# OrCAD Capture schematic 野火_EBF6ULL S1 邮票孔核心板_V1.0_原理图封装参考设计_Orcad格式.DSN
size B; title: 野火_EBF6ULL S1 邮票孔核心板; rev: V1.0; note: MCU_连接器
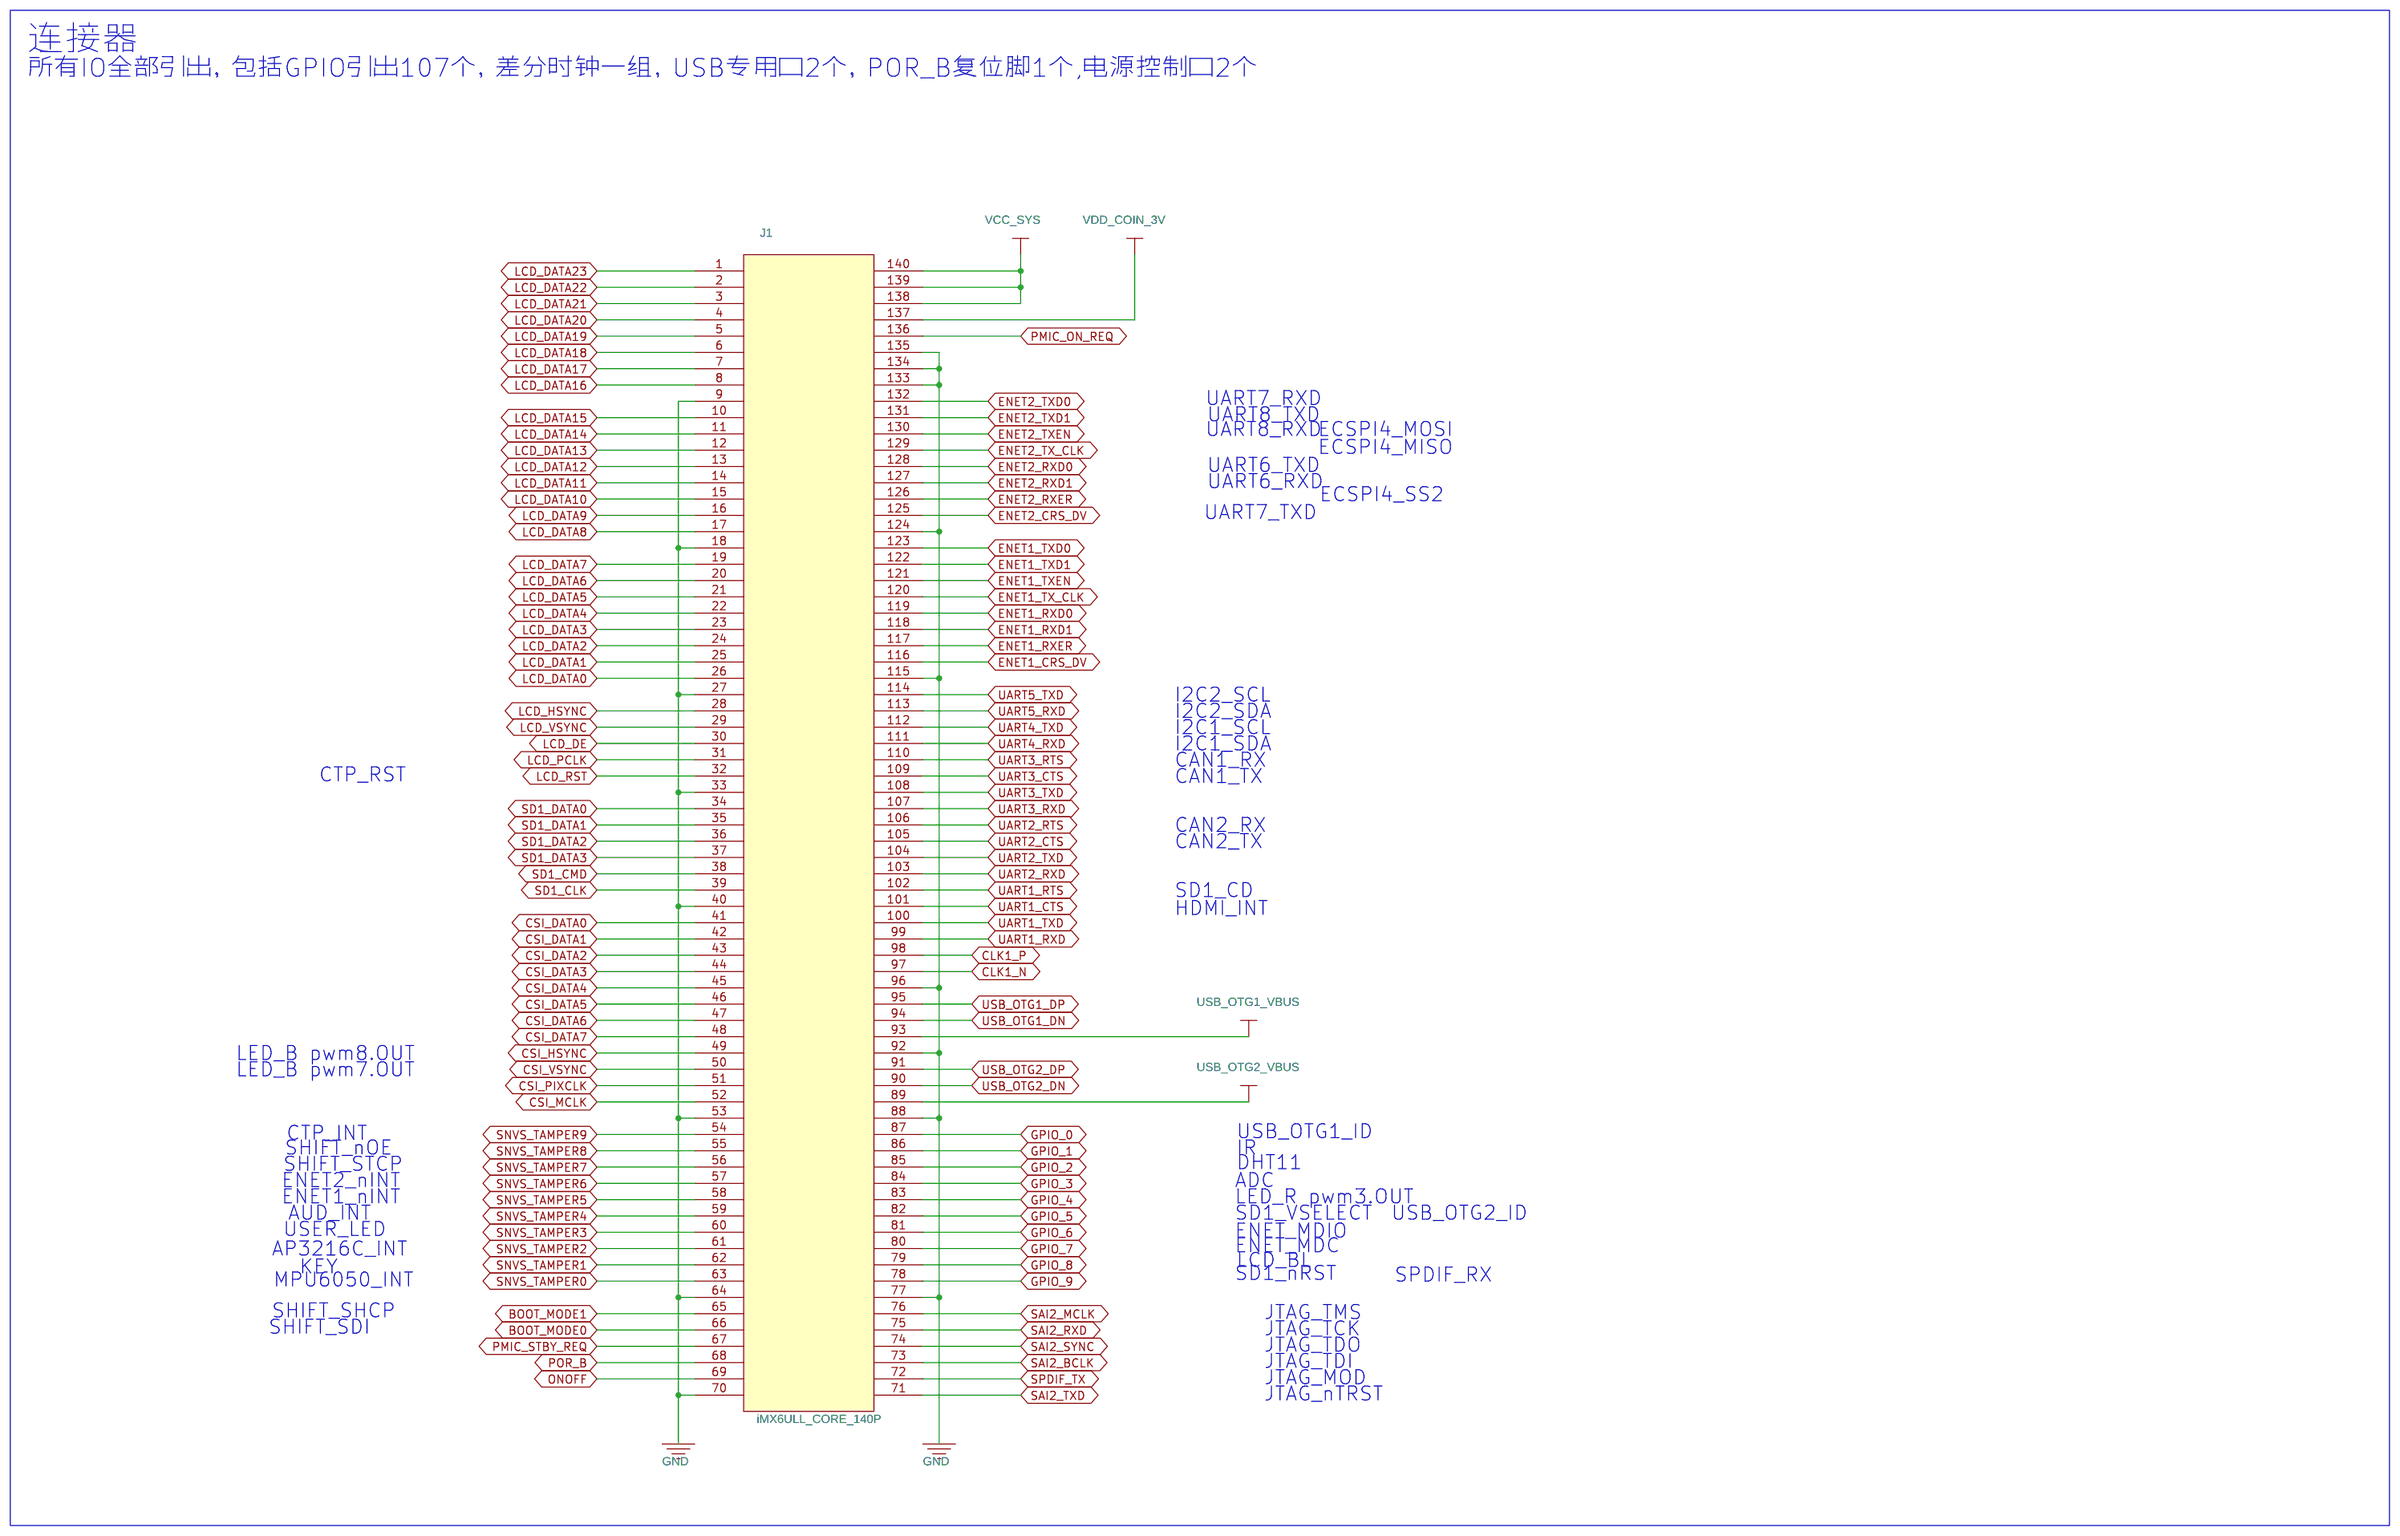
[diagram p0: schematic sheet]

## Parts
J1  iMX6ULL_CORE_140P  [6ULL_CORE_140P_39X39]

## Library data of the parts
J1 = iMX6ULL_CORE_140P

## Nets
GND: J1.9 J1.18 J1.27 J1.33 J1.40 J1.53 J1.64 J1.70 J1.77 J1.88 J1.92 J1.96 J1.115 J1.124 J1.133 J1.134 J1.135
VCC_SYS: J1.138 J1.139 J1.140
VDD_COIN_3V: J1.137
BOOT_MODE0: J1.66
BOOT_MODE1: J1.65
CLK1_N: J1.97
CLK1_P: J1.98
CSI_DATA0: J1.41
CSI_DATA1: J1.42
CSI_DATA2: J1.43
CSI_DATA3: J1.44
CSI_DATA4: J1.45
CSI_DATA5: J1.46
CSI_DATA6: J1.47
CSI_DATA7: J1.48
CSI_HSYNC: J1.49
CSI_MCLK: J1.52
CSI_PIXCLK: J1.51
CSI_VSYNC: J1.50
ENET1_CRS_DV: J1.116
ENET1_RXD0: J1.119
ENET1_RXD1: J1.118
ENET1_RXER: J1.117
ENET1_TX_CLK: J1.120
ENET1_TXD0: J1.123
ENET1_TXD1: J1.122
ENET1_TXEN: J1.121
ENET2_CRS_DV: J1.125
ENET2_RXD0: J1.128
ENET2_RXD1: J1.127
ENET2_RXER: J1.126
ENET2_TX_CLK: J1.129
ENET2_TXD0: J1.132
ENET2_TXD1: J1.131
ENET2_TXEN: J1.130
GPIO_0: J1.87
GPIO_1: J1.86
GPIO_2: J1.85
GPIO_3: J1.84
GPIO_4: J1.83
GPIO_5: J1.82
GPIO_6: J1.81
GPIO_7: J1.80
GPIO_8: J1.79
GPIO_9: J1.78
LCD_DATA0: J1.26
LCD_DATA1: J1.25
LCD_DATA2: J1.24
LCD_DATA3: J1.23
LCD_DATA4: J1.22
LCD_DATA5: J1.21
LCD_DATA6: J1.20
LCD_DATA7: J1.19
LCD_DATA8: J1.17
LCD_DATA9: J1.16
LCD_DATA10: J1.15
LCD_DATA11: J1.14
LCD_DATA12: J1.13
LCD_DATA13: J1.12
LCD_DATA14: J1.11
LCD_DATA15: J1.10
LCD_DATA16: J1.8
LCD_DATA17: J1.7
LCD_DATA18: J1.6
LCD_DATA19: J1.5
LCD_DATA20: J1.4
LCD_DATA21: J1.3
LCD_DATA22: J1.2
LCD_DATA23: J1.1
LCD_DE: J1.30
LCD_HSYNC: J1.28
LCD_PCLK: J1.31
LCD_RST: J1.32
LCD_VSYNC: J1.29
ONOFF: J1.69
PMIC_ON_REQ: J1.136
PMIC_STBY_REQ: J1.67
POR_B: J1.68
SAI2_BCLK: J1.73
SAI2_MCLK: J1.76
SAI2_RXD: J1.75
SAI2_SYNC: J1.74
SAI2_TXD: J1.71
SD1_CLK: J1.39
SD1_CMD: J1.38
SD1_DATA0: J1.34
SD1_DATA1: J1.35
SD1_DATA2: J1.36
SD1_DATA3: J1.37
SNVS_TAMPER0: J1.63
SNVS_TAMPER1: J1.62
SNVS_TAMPER2: J1.61
SNVS_TAMPER3: J1.60
SNVS_TAMPER4: J1.59
SNVS_TAMPER5: J1.58
SNVS_TAMPER6: J1.57
SNVS_TAMPER7: J1.56
SNVS_TAMPER8: J1.55
SNVS_TAMPER9: J1.54
SPDIF_TX: J1.72
UART1_CTS: J1.101
UART1_RTS: J1.102
UART1_RXD: J1.99
UART1_TXD: J1.100
UART2_CTS: J1.105
UART2_RTS: J1.106
UART2_RXD: J1.103
UART2_TXD: J1.104
UART3_CTS: J1.109
UART3_RTS: J1.110
UART3_RXD: J1.107
UART3_TXD: J1.108
UART4_RXD: J1.111
UART4_TXD: J1.112
UART5_RXD: J1.113
UART5_TXD: J1.114
USB_OTG1_DN: J1.94
USB_OTG1_DP: J1.95
USB_OTG1_VBUS: J1.93
USB_OTG2_DN: J1.90
USB_OTG2_DP: J1.91
USB_OTG2_VBUS: J1.89

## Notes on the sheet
- 连接器
- 所有IO全部引出，包括GPIO引出107个，差分时钟一组，USB专用口2个，POR_B复位脚1个,电源控制口2个
- UART7_RXD
- UART8_TXD
- UART8_RXD
- ECSPI4_MISO
- ECSPI4_MOSI
- UART6_TXD
- UART6_RXD
- ECSPI4_SS2
- UART7_TXD
- I2C2_SCL
- I2C2_SDA
- I2C1_SCL
- I2C1_SDA
- CTP_RST
- CAN1_RX
- CAN1_TX
- CAN2_RX
- CAN2_TX
- SD1_CD
- HDMI_INT
- LED_B pwm8.OUT
- LED_B pwm7.OUT
- CTP_INT
- USB_OTG1_ID
- SHIFT_nOE
- IR
- SHIFT_STCP
- DHT11
- ENET1_nINT
- ENET2_nINT
- ADC
- LED_R pwm3.OUT
- AUD_INT
- SD1_VSELECT
- USB_OTG2_ID
- USER_LED
- ENET_MDIO
- AP3216C_INT
- ENET_MDC
- KEY
- SD1_nRST
- LCD_BL
- SPDIF_RX
- MPU6050_INT
- SHIFT_SHCP
- JTAG_TMS
- SHIFT_SDI
- JTAG_TCK
- JTAG_TDO
- JTAG_TDI
- JTAG_MOD
- JTAG_nTRST
